(* Logix 5000 project; controller MVI56ADMSerialOut 1756-L63 rev 11.1; software revision 11.13 *)
// Example Logic for the MVI56-ADM module.

TASK MainTask (task) : MainProgram

MODULES
   Local : 1756-L63 (rev 11.1)
      ADM : vendor 1 type 0 code 15 (rev 1.1, Output RPI 2 ms)
END_MODULES

TYPE ADMModuleDef :
STRUCT
   ReadData : INT[600];
   WriteData : INT[600];
END_STRUCT
END_TYPE

VAR_GLOBAL   (* controller tags *)
   ADM : ADMModuleDef;
   MJFAULTS : DINT[12] := ([0] := -491726278, [1] := 191080, [3] := -495837906, [4] := 191080);
   Port2Count : INT := 2006;
   SendDataPort1 : BOOL;
   SendDataPort2 : BOOL;
   SerialCount : INT := 1;
END_VAR

PROGRAM MainProgram   (* routine attr 65 MainRoutine *)

ROUTINE MainRoutine   (* ladder *)
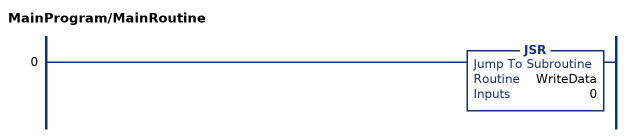
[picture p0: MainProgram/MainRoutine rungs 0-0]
   0: JSR(WriteData,0);
END_ROUTINE

ROUTINE WriteData   (* ladder *)
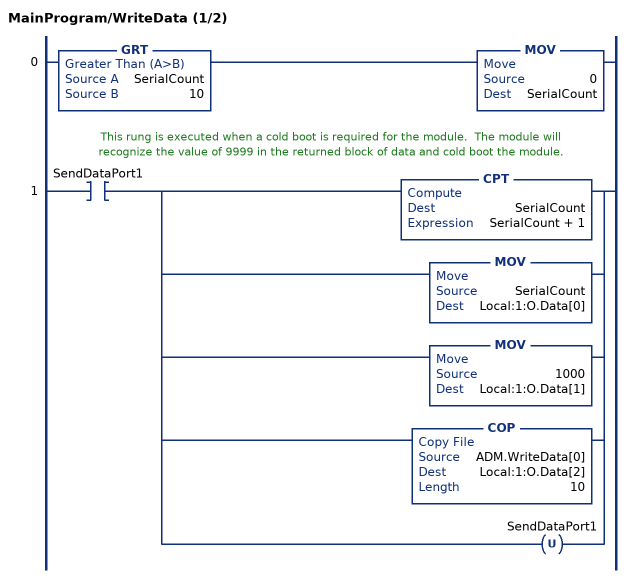
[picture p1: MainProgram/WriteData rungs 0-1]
   0: GRT(SerialCount,10)MOV(0,SerialCount);
   // This rung is executed when a cold boot is required for the module.  The module will recognize the value of 9999 in the returned block of data and cold boot the module.
   1: XIC(SendDataPort1)[CPT(SerialCount,SerialCount + 1) ,MOV(SerialCount,Local:1:O.Data[0]) ,MOV(1000,Local:1:O.Data[1]) ,COP(ADM.WriteData[0],Local:1:O.Data[2],10) ,OTU(SendDataPort1) ];
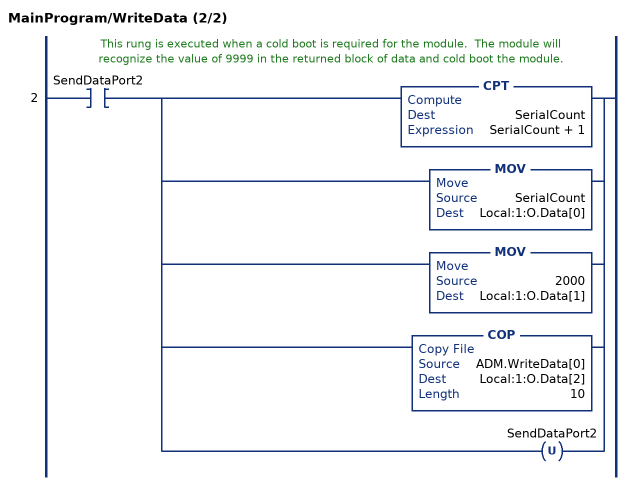
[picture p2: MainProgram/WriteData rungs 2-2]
   // This rung is executed when a cold boot is required for the module.  The module will recognize the value of 9999 in the returned block of data and cold boot the module.
   2: XIC(SendDataPort2)[CPT(SerialCount,SerialCount + 1) ,MOV(SerialCount,Local:1:O.Data[0]) ,MOV(2000,Local:1:O.Data[1]) ,COP(ADM.WriteData[0],Local:1:O.Data[2],10) ,OTU(SendDataPort2) ];
END_ROUTINE
END_PROGRAM

PROGRAM StartUp   (* routine attr 65 PowerUp *)

ROUTINE PowerUp   (* ladder *)
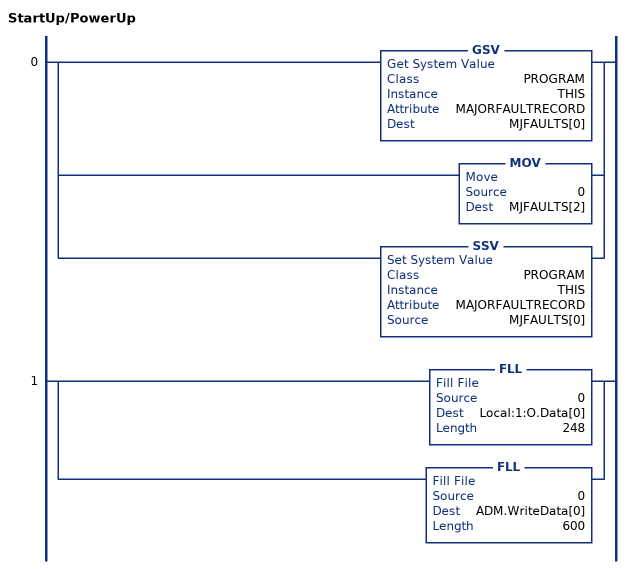
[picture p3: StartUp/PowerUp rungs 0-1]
   0: [GSV(PROGRAM,THIS,MAJORFAULTRECORD,MJFAULTS[0]) ,MOV(0,MJFAULTS[2]) ,SSV(PROGRAM,THIS,MAJORFAULTRECORD,MJFAULTS[0]) ];
   1: [FLL(0,Local:1:O.Data[0],248) ,FLL(0,ADM.WriteData[0],600) ];
END_ROUTINE
END_PROGRAM
